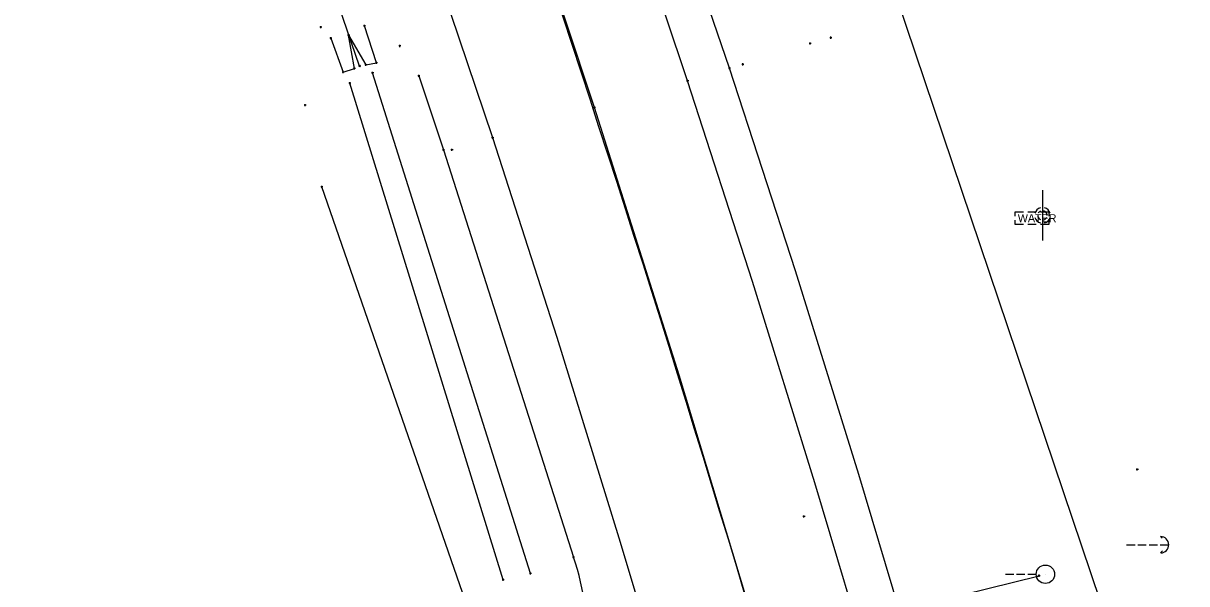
# Model space of a CAD drawing. Extents: x 1954856 to 2011933, y 399149 to 426294.
# Drawn here: x 2004956.3 to 2005094.5, y 407723 to 407789.5 of the extents above; entities that cross this region are included whole.
import ezdxf

# ---------------------------------------------------------------- set-up
doc = ezdxf.new("R2010")
doc.units = 0
for name, color, linetype in [('BankMent_ep', 7, 'Continuous'), ('BaselineSurvey', 7, 'Continuous'), ('ElecAer_ep', 7, 'Continuous'), ('EndTreatMES_ep', 7, 'Continuous'), ('FlowLineInvert_ep', 7, 'Continuous'), ('GuyWireAnchor_ep', 7, 'Continuous'), ('GuyWirePole_ep', 7, 'Continuous'), ('MeterWater_ep', 7, 'Continuous'), ('PavtAsphalt_ep', 7, 'Continuous'), ('PavtAsphaltCrown_ep', 7, 'Continuous'), ('PipeCulvert_ep', 7, 'Continuous'), ('PointLocator_ep', 7, 'Continuous'), ('ShldrPaved_ep', 7, 'Continuous'), ('TreeLineScatter_ep', 7, 'Continuous'), ('WaterFct_ep', 7, 'Continuous')]:
    doc.layers.add(name, color=color, linetype=linetype)

msp = doc.modelspace()

# ---------------------------------------------------------------- linework, layer by layer
at = {"layer": 'BankMent_ep'}
for p, q in [((2005003.3, 407783.28), (2005006.24, 407774.5)), ((2005006.24, 407774.5), (2005021.67, 407726.14)), ((2005011.02, 407714.64), (2004991.78, 407770.11))]:
    msp.add_line(p, q, dxfattribs=at)
for points in [[(2005016.56, 407724.19), (2004997.81, 407783.66)], [(2005013.3, 407723.46), (2004995.1, 407782.42)]]:
    msp.add_lwpolyline(points, dxfattribs=at)
msp.add_arc((2004994.57, 407716.86), 28.64, 354.6456, 18.8935, dxfattribs=at)
at = {"layer": 'BaselineSurvey'}
msp.add_arc((2002584.46, 406985.33), 2565.51, 11.93882, 21.72713, dxfattribs=at)
msp.add_arc((2002584.46, 406985.33), 2565.51, 11.93882, 21.72713, dxfattribs=at)
at = {"layer": 'ElecAer_ep'}
msp.add_lwpolyline([(2005012.78, 407708.09), (2005076.94, 407723.93)], dxfattribs=at)
at = {"layer": 'EndTreatMES_ep'}
for p, q in [((2004998.27, 407784.84), (2004996.84, 407789.22)), ((2004992.85, 407787.78), (2004994.29, 407783.72)), ((2004995.66, 407784.17), (2004994.96, 407788.12)), ((2004994.96, 407788.12), (2004997.01, 407784.59)), ((2004997.01, 407784.59), (2004998.27, 407784.84)), ((2004994.29, 407783.72), (2004995.66, 407784.17))]:
    msp.add_line(p, q, dxfattribs=at)
at = {"layer": 'FlowLineInvert_ep'}
for p, q in [((2004996.35, 407784.36), (2004996.17, 407784.53)), ((2004996.35, 407784.53), (2004996.17, 407784.36)), ((2004996.26, 407784.45), (2004996.26, 407784.45))]:
    msp.add_line(p, q, dxfattribs=at)
at = {"layer": 'GuyWireAnchor_ep'}
for p, q in [((2005091.36, 407728.58), (2005091.56, 407728.39)), ((2005087.34, 407727.62), (2005088.34, 407727.62)), ((2005088.67, 407727.62), (2005089.67, 407727.62)), ((2005090, 407727.62), (2005091, 407727.62)), ((2005091.34, 407727.61), (2005092.34, 407727.61)), ((2005091.38, 407726.64), (2005091.62, 407726.87)), ((2005092.34, 407727.61), (2005092.34, 407727.61))]:
    msp.add_line(p, q, dxfattribs=at)
msp.add_arc((2005091.37, 407727.61), 0.973, 271.14, 90.0059, dxfattribs=at)
at = {"layer": 'GuyWirePole_ep'}
for p, q in [((2005072.94, 407724.11), (2005073.94, 407724.11)), ((2005074.27, 407724.11), (2005075.27, 407724.11)), ((2005075.61, 407724.11), (2005076.61, 407724.11)), ((2005077.7, 407724.11), (2005077.7, 407724.11))]:
    msp.add_line(p, q, dxfattribs=at)
msp.add_circle((2005077.7, 407724.11), 1.09, dxfattribs=at)
at = {"layer": 'MeterWater_ep'}
msp.add_line((2005076.11, 407766.39), (2005076.11, 407766.39), dxfattribs=at)
for points in [[(2005074.11, 407766.64), (2005074.11, 407767.14), (2005075.11, 407767.14)], [(2005075.61, 407767.14), (2005076.61, 407767.14)], [(2005077.11, 407767.14), (2005078.11, 407767.14), (2005078.11, 407766.64)], [(2005075.11, 407765.64), (2005074.11, 407765.64), (2005074.11, 407766.14)], [(2005076.61, 407765.64), (2005075.61, 407765.64)], [(2005078.11, 407766.14), (2005078.11, 407765.64), (2005077.11, 407765.64)]]:
    msp.add_lwpolyline(points, dxfattribs=at)
at = {"layer": 'PavtAsphalt_ep'}
for points in [[(2005064.38, 407686.9), (2005057.48, 407710.97), (2005050.32, 407734.96), (2005042.9, 407758.87), (2005035.21, 407782.68), (2005027.26, 407806.35), (2005019.06, 407829.93), (2005010.67, 407853.44), (2005002.12, 407876.9), (2004994.47, 407897.59), (2004986.75, 407918.26), (2004978.98, 407938.91)], [(2005041.13, 407680.55), (2005034.23, 407704.51), (2005027.1, 407728.4), (2005019.72, 407752.21), (2005012.06, 407775.92), (2005004.14, 407799.5), (2004995.99, 407823.01), (2004987.66, 407846.45), (2004979.2, 407869.85), (2004971.68, 407890.4), (2004964.07, 407910.91), (2004956.32, 407931.37)]]:
    msp.add_lwpolyline(points, dxfattribs=at)
at = {"layer": 'PavtAsphaltCrown_ep'}
msp.add_lwpolyline([(2005053.04, 407683.78), (2005043.84, 407715.84), (2005034.2, 407747.75), (2005024.14, 407779.53), (2005013.67, 407811.16), (2005002.75, 407842.63), (2004991.37, 407873.93), (2004983.64, 407894.42), (2004975.8, 407914.86), (2004967.93, 407935.3)], dxfattribs=at)
at = {"layer": 'PipeCulvert_ep'}
msp.add_lwpolyline([(2004996.26, 407784.45), (2004975.05, 407846.37)], dxfattribs=at)
at = {"layer": 'PointLocator_ep'}
for p, q in [((2004991.79, 407789.07), (2004991.54, 407789.07)), ((2004991.67, 407788.95), (2004991.67, 407789.2)), ((2004991.67, 407789.07), (2004991.67, 407789.07)), ((2004996.97, 407789.22), (2004996.72, 407789.22)), ((2004996.84, 407789.1), (2004996.84, 407789.35)), ((2004996.84, 407789.22), (2004996.84, 407789.22)), ((2004992.98, 407787.78), (2004992.73, 407787.78)), ((2004992.85, 407787.65), (2004992.85, 407787.9)), ((2004992.85, 407787.78), (2004992.85, 407787.78)), ((2004995.09, 407788.12), (2004994.84, 407788.12)), ((2004994.96, 407788), (2004994.96, 407788.25)), ((2004994.96, 407788.12), (2004994.96, 407788.12)), ((2005052.34, 407787.82), (2005052.09, 407787.82)), ((2005052.22, 407787.7), (2005052.22, 407787.95)), ((2005052.22, 407787.82), (2005052.22, 407787.82)), ((2005001.17, 407786.84), (2005000.92, 407786.84)), ((2005001.04, 407786.71), (2005001.04, 407786.96)), ((2005001.04, 407786.84), (2005001.04, 407786.84)), ((2005049.88, 407787.13), (2005049.63, 407787.13)), ((2005049.75, 407787.01), (2005049.75, 407787.26)), ((2005049.75, 407787.13), (2005049.75, 407787.13)), ((2004997.01, 407784.47), (2004997.01, 407784.72)), ((2004998.4, 407784.84), (2004998.15, 407784.84)), ((2004998.27, 407784.72), (2004998.27, 407784.97)), ((2004998.27, 407784.84), (2004998.27, 407784.84)), ((2005041.89, 407784.65), (2005041.64, 407784.65)), ((2005041.77, 407784.53), (2005041.77, 407784.78)), ((2005041.77, 407784.65), (2005041.77, 407784.65)), ((2004994.42, 407783.72), (2004994.17, 407783.72)), ((2004994.29, 407783.6), (2004994.29, 407783.85)), ((2004994.29, 407783.72), (2004994.29, 407783.72)), ((2004995.78, 407784.17), (2004995.53, 407784.17)), ((2004995.66, 407784.04), (2004995.66, 407784.29)), ((2004995.66, 407784.17), (2004995.66, 407784.17)), ((2004997.13, 407784.59), (2004996.88, 407784.59)), ((2004997.01, 407784.59), (2004997.01, 407784.59)), ((2004997.94, 407783.66), (2004997.69, 407783.66)), ((2004997.81, 407783.53), (2004997.81, 407783.78)), ((2004997.81, 407783.66), (2004997.81, 407783.66)), ((2005003.42, 407783.28), (2005003.17, 407783.28)), ((2005003.3, 407783.16), (2005003.3, 407783.41)), ((2005003.3, 407783.28), (2005003.3, 407783.28)), ((2005040.32, 407784.19), (2005040.07, 407784.19)), ((2005040.2, 407784.07), (2005040.2, 407784.32)), ((2005040.2, 407784.19), (2005040.2, 407784.19)), ((2004995.23, 407782.42), (2004994.98, 407782.42)), ((2004995.1, 407782.29), (2004995.1, 407782.54)), ((2004995.1, 407782.42), (2004995.1, 407782.42)), ((2005035.34, 407782.68), (2005035.09, 407782.68)), ((2005035.21, 407782.56), (2005035.21, 407782.81)), ((2005035.21, 407782.68), (2005035.21, 407782.68)), ((2004989.93, 407779.82), (2004989.68, 407779.82)), ((2004989.8, 407779.69), (2004989.8, 407779.94)), ((2004989.8, 407779.82), (2004989.8, 407779.82)), ((2005024.27, 407779.53), (2005024.02, 407779.53)), ((2005024.14, 407779.41), (2005024.14, 407779.66)), ((2005024.14, 407779.53), (2005024.14, 407779.53)), ((2005012.19, 407775.92), (2005011.94, 407775.92)), ((2005012.06, 407775.8), (2005012.06, 407776.05)), ((2005012.06, 407775.92), (2005012.06, 407775.92)), ((2005006.36, 407774.5), (2005006.11, 407774.5)), ((2005006.24, 407774.37), (2005006.24, 407774.62)), ((2005006.24, 407774.5), (2005006.24, 407774.5)), ((2005007.35, 407774.5), (2005007.1, 407774.5)), ((2005007.23, 407774.38), (2005007.23, 407774.63)), ((2005007.23, 407774.5), (2005007.23, 407774.5)), ((2004991.9, 407770.11), (2004991.65, 407770.11)), ((2004991.78, 407769.98), (2004991.78, 407770.23)), ((2004991.78, 407770.11), (2004991.78, 407770.11)), ((2005088.74, 407736.53), (2005088.49, 407736.53)), ((2005088.61, 407736.41), (2005088.61, 407736.66)), ((2005088.61, 407736.53), (2005088.61, 407736.53)), ((2005049.15, 407730.98), (2005048.9, 407730.98)), ((2005049.03, 407730.85), (2005049.03, 407731.1)), ((2005049.03, 407730.98), (2005049.03, 407730.98)), ((2005021.79, 407726.14), (2005021.54, 407726.14)), ((2005021.67, 407726.01), (2005021.67, 407726.26)), ((2005021.67, 407726.14), (2005021.67, 407726.14)), ((2005016.68, 407724.19), (2005016.43, 407724.19)), ((2005016.56, 407724.07), (2005016.56, 407724.32)), ((2005016.56, 407724.19), (2005016.56, 407724.19)), ((2005077.06, 407723.93), (2005076.81, 407723.93)), ((2005076.94, 407723.81), (2005076.94, 407724.06)), ((2005076.94, 407723.93), (2005076.94, 407723.93)), ((2005013.43, 407723.46), (2005013.18, 407723.46)), ((2005013.3, 407723.34), (2005013.3, 407723.59)), ((2005013.3, 407723.46), (2005013.3, 407723.46))]:
    msp.add_line(p, q, dxfattribs=at)
at = {"layer": 'ShldrPaved_ep'}
msp.add_lwpolyline([(2005069.77, 407687.36), (2005062.79, 407711.7), (2005055.56, 407735.97), (2005048.04, 407760.13), (2005040.2, 407784.19), (2005032.08, 407807.92), (2005023.72, 407831.57), (2005015.21, 407855.18), (2005006.69, 407878.78), (2004999.23, 407899.49), (2004991.68, 407920.16), (2004983.86, 407940.74)], dxfattribs=at)
at = {"layer": 'TreeLineScatter_ep'}
msp.add_lwpolyline([(2005090.8, 407701.38), (2005050.19, 407821.81)], dxfattribs=at)
at = {"layer": 'WaterFct_ep'}
for p, q in [((2005077.35, 407769.72), (2005077.35, 407763.72)), ((2005077.35, 407766.72), (2005077.35, 407766.72))]:
    msp.add_line(p, q, dxfattribs=at)
for radius, start, end in [(0.937, 105.466, 164.534), (0.562, 180, 243.6122), (0.562, 116.3878, 153.6122), (0.562, 0, 90), (0.937, 15.466, 74.534), (0.937, 195.466, 254.534), (0.562, 270, 333.6122), (0.937, 285.466, 344.534)]:
    msp.add_arc((2005077.35, 407766.72), radius, start, end, dxfattribs=at)

# ---------------------------------------------------------------- texts
at = {"layer": 'MeterWater_ep'}
msp.add_text('WATER', height=0.95, dxfattribs=at).set_placement((2005074.42, 407765.91))

doc.saveas('drawing.dxf')
